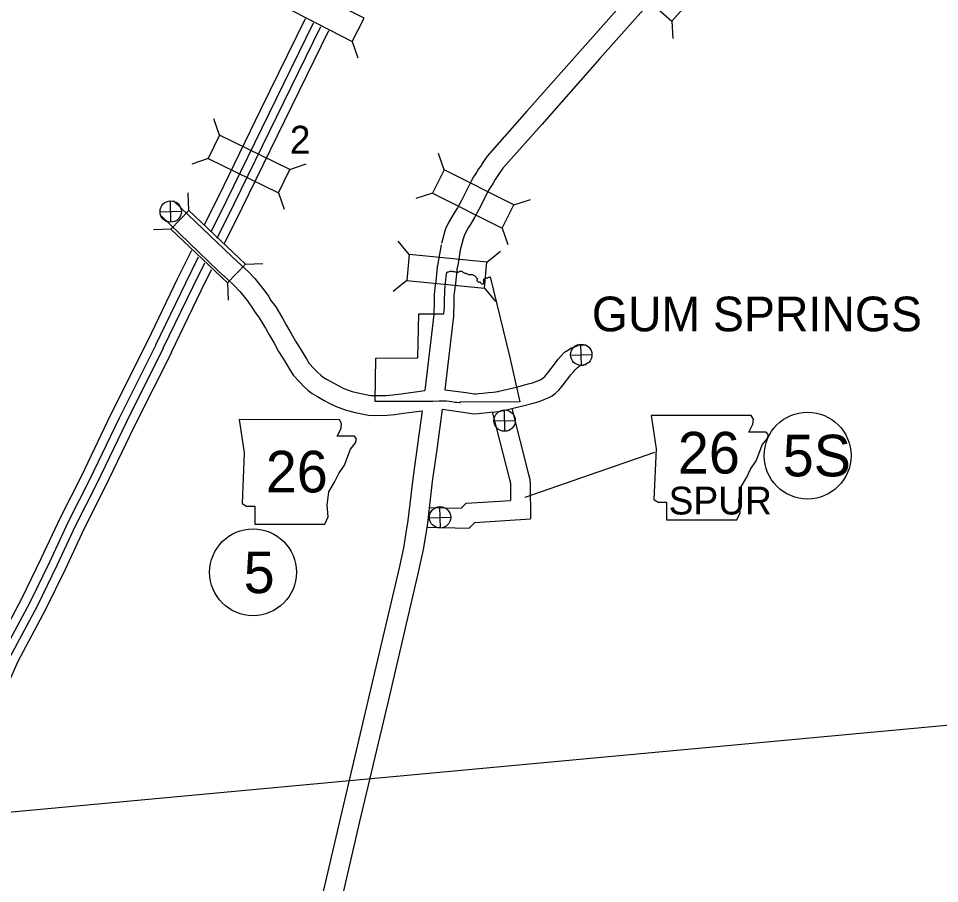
# Model space of a CAD drawing. Extents: x 1369979 to 1371646, y 379997 to 381064.
# Drawn here: x 1370321.9 to 1370431.4, y 380878.2 to 380981.1 of the extents above; entities that cross this region are included whole.
import ezdxf

# ---------------------------------------------------------------- set-up
doc = ezdxf.new("R2010")
doc.units = 0
doc.layers.add('R_Border Notes', color=7, linetype='Continuous')
doc.layers.add('R_Draft', color=7, linetype='Continuous')

msp = doc.modelspace()

# ---------------------------------------------------------------- linework, layer by layer
at = {"layer": 'R_Border Notes'}
for p, q in [((1370399.53, 380980.71), (1370399.66, 380978.65)), ((1370361.57, 380978.31), (1370362.21, 380976.35)), ((1370345.8, 380967.18), (1370345.13, 380969.13)), ((1370372.47, 380963.05), (1370371.82, 380965)), ((1370344.44, 380964.4), (1370342.49, 380963.73)), ((1370354.14, 380963.11), (1370356.09, 380963.78)), ((1370342.13, 380958.24), (1370342.07, 380960.31)), ((1370352.79, 380960.33), (1370353.46, 380958.38)), ((1370371.09, 380960.28), (1370369.13, 380959.63)), ((1370340.02, 380956.82), (1370339.97, 380959.37)), ((1370380.77, 380958.89), (1370382.73, 380959.54)), ((1370338.72, 380958.07), (1370341.27, 380958.13)), ((1370340, 380956), (1370337.94, 380955.94)), ((1370379.39, 380956.12), (1370380.04, 380954.17)), ((1370368.34, 380952.98), (1370367.03, 380954.57)), ((1370377.57, 380952.07), (1370379.17, 380953.38)), ((1370348.87, 380951.86), (1370350.93, 380951.92)), ((1370346.74, 380949.62), (1370346.8, 380947.55)), ((1370368.03, 380949.9), (1370366.44, 380948.59)), ((1370377.27, 380948.99), (1370378.58, 380947.4)), ((1370388.8, 380939.8), (1370388.74, 380942.34)), ((1370387.49, 380941.04), (1370390.04, 380941.1)), ((1370379.7, 380931.97), (1370379.64, 380934.52)), ((1370378.4, 380933.22), (1370380.94, 380933.27)), ((1370382.12, 380924.14), (1370397.5, 380929.49)), ((1370372.03, 380920.46), (1370371.97, 380923.01)), ((1370370.73, 380921.71), (1370373.28, 380921.76))]:
    msp.add_line(p, q, dxfattribs=at)
for points in [[(1370392.59, 380986.86), (1370399.53, 380980.71), (1370401.59, 380983.02), (1370394.64, 380989.18)], [(1370362.98, 380981.07), (1370354.71, 380985.28), (1370353.31, 380982.53), (1370361.57, 380978.31)], [(1370354.14, 380963.11), (1370345.8, 380967.18), (1370344.44, 380964.4), (1370352.79, 380960.33)], [(1370380.77, 380958.89), (1370372.47, 380963.05), (1370371.09, 380960.28), (1370379.39, 380956.12)], [(1370348.87, 380951.86), (1370342.13, 380958.24), (1370340, 380956), (1370346.74, 380949.62)], [(1370377.57, 380952.07), (1370368.34, 380952.98), (1370368.03, 380949.9), (1370377.27, 380948.99)], [(1370348.14, 380933.37), (1370348.73, 380929.4), (1370348.47, 380923.39), (1370349, 380923.06), (1370349.99, 380923.06), (1370349.99, 380920.94), (1370358.32, 380920.94), (1370358.71, 380921.8), (1370358.58, 380923.19), (1370358.78, 380924.78), (1370359.51, 380926.03), (1370359.97, 380926.96), (1370360.63, 380927.95), (1370361.03, 380929.01), (1370361.36, 380929.86), (1370361.95, 380930.59), (1370362.08, 380931.05), (1370361.82, 380931.38), (1370359.77, 380931.38), (1370360.23, 380932.31), (1370360.3, 380932.9), (1370360.03, 380933.36)], [(1370397.07, 380933.87), (1370397.66, 380929.9), (1370397.4, 380923.89), (1370397.93, 380923.56), (1370398.92, 380923.56), (1370398.92, 380921.44), (1370407.25, 380921.44), (1370407.64, 380922.3), (1370407.51, 380923.69), (1370407.71, 380925.27), (1370408.44, 380926.53), (1370408.9, 380927.46), (1370409.56, 380928.45), (1370409.96, 380929.5), (1370410.29, 380930.36), (1370410.88, 380931.09), (1370411.01, 380931.55), (1370410.75, 380931.88), (1370408.7, 380931.88), (1370409.16, 380932.81), (1370409.23, 380933.4), (1370408.96, 380933.86)]]:
    msp.add_lwpolyline(points, close=True, dxfattribs=at)
for points in [[(1370397.99, 380987.73), (1370389.22, 380977.83), (1370382.32, 380970.01), (1370377.6, 380964.69), (1370377.08, 380963.91), (1370376.79, 380963.47), (1370376.57, 380963.17), (1370376.33, 380962.75), (1370376.16, 380962.5), (1370375.98, 380962.24), (1370375.73, 380961.8), (1370374.54, 380959.43), (1370374.06, 380958.54), (1370373.65, 380957.86), (1370373.35, 380957.38), (1370372.97, 380956.72), (1370372.65, 380956.05), (1370372.49, 380955.5), (1370372.15, 380954.28)], [(1370399.74, 380986.17), (1370390.98, 380976.28), (1370384.07, 380968.45), (1370379.46, 380963.26), (1370379.03, 380962.61), (1370378.71, 380962.14), (1370378.55, 380961.91), (1370378.31, 380961.49), (1370378.09, 380961.17), (1370377.97, 380961), (1370377.79, 380960.69), (1370376.62, 380958.34), (1370376.09, 380957.39), (1370375.65, 380956.64), (1370375.35, 380956.16), (1370375.05, 380955.64), (1370374.85, 380955.22), (1370374.74, 380954.85), (1370374.41, 380953.65)], [(1370343.98, 380956.49), (1370345.69, 380959.93), (1370350.7, 380970.21), (1370356, 380981.04)], [(1370344.78, 380955.69), (1370346.65, 380959.46), (1370351.67, 380969.74), (1370356.96, 380980.54)], [(1370345.5, 380954.93), (1370347.53, 380959.02), (1370352.55, 380969.31), (1370357.82, 380980.09)], [(1370346.34, 380954.21), (1370348.49, 380958.55), (1370353.51, 380968.84), (1370358.79, 380979.62)], [(1370340.34, 380959.39), (1370347.27, 380952.74), (1370348.38, 380951.73), (1370349.18, 380950.96), (1370349.97, 380950.13), (1370350.41, 380949.59), (1370350.93, 380948.96), (1370351.6, 380948.02), (1370351.89, 380947.54), (1370352.47, 380946.79), (1370353.29, 380945.41), (1370353.75, 380944.57), (1370354.32, 380943.59), (1370354.8, 380942.69), (1370355.38, 380941.81), (1370356.13, 380940.59), (1370356.45, 380940.04), (1370356.98, 380939.46), (1370357.48, 380938.95), (1370357.81, 380938.64), (1370358.1, 380938.43), (1370358.52, 380938.18), (1370359.44, 380937.65), (1370359.96, 380937.37), (1370360.56, 380937.08), (1370361.55, 380936.72), (1370362.42, 380936.5), (1370363.18, 380936.34), (1370363.75, 380936.23), (1370364.34, 380936.22), (1370365.6, 380936.25), (1370366.38, 380936.31), (1370367.36, 380936.45), (1370370.18, 380936.81)], [(1370338.72, 380957.7), (1370345.68, 380951.02), (1370346.78, 380950.02), (1370347.52, 380949.31), (1370348.21, 380948.58), (1370348.6, 380948.1), (1370349.07, 380947.53), (1370349.64, 380946.73), (1370349.96, 380946.21), (1370350.52, 380945.47), (1370351.26, 380944.24), (1370351.7, 380943.43), (1370352.27, 380942.45), (1370352.79, 380941.48), (1370353.4, 380940.56), (1370354.12, 380939.38), (1370354.56, 380938.64), (1370355.28, 380937.85), (1370355.84, 380937.27), (1370356.32, 380936.83), (1370356.81, 380936.46), (1370357.35, 380936.15), (1370358.29, 380935.61), (1370358.89, 380935.28), (1370359.65, 380934.92), (1370360.85, 380934.48), (1370361.89, 380934.22), (1370362.72, 380934.04), (1370363.5, 380933.89), (1370364.35, 380933.87), (1370365.72, 380933.91), (1370366.63, 380933.98), (1370367.67, 380934.13), (1370369.87, 380934.41)], [(1370372.12, 380954.16), (1370371.82, 380952.35), (1370371.68, 380951.7), (1370371.65, 380951.56), (1370371.63, 380951.07), (1370371.59, 380950.62), (1370371.5, 380949.82), (1370371.39, 380949.05), (1370371.28, 380948.19), (1370371.3, 380946.96), (1370371.26, 380946.26), (1370371.25, 380945.87), (1370370.18, 380936.81)], [(1370374.43, 380953.77), (1370374.13, 380951.91), (1370373.98, 380951.26), (1370373.98, 380950.93), (1370373.92, 380950.38), (1370373.83, 380949.53), (1370373.72, 380948.73), (1370373.63, 380948.06), (1370373.65, 380946.91), (1370373.6, 380946.14), (1370373.58, 380945.68), (1370372.55, 380936.92)], [(1370337.26, 380942.73), (1370340.81, 380950.1), (1370342.5, 380953.52)], [(1370338.23, 380942.27), (1370341.77, 380949.63), (1370343.31, 380952.72)], [(1370339.11, 380941.84), (1370342.65, 380949.2), (1370344.05, 380952.02)], [(1370340.08, 380941.38), (1370343.61, 380948.73), (1370344.85, 380951.22)], [(1370377.96, 380950.35), (1370380.27, 380940.75), (1370381.47, 380935.48), (1370374.33, 380935.43), (1370374.33, 380935.35), (1370374.27, 380935.36), (1370373.99, 380935.39), (1370373.77, 380935.41), (1370373.39, 380935.47), (1370373.06, 380935.52), (1370372.75, 380935.55), (1370372.41, 380935.57), (1370371.88, 380935.56), (1370371.13, 380935.53), (1370364.29, 380935.52), (1370364.35, 380940.68), (1370369.36, 380940.7), (1370369.46, 380945.93), (1370372.46, 380945.94)], [(1370372.46, 380945.94), (1370372.49, 380946.33), (1370372.52, 380946.79), (1370372.53, 380947.26), (1370372.54, 380947.71), (1370372.56, 380948.39), (1370372.58, 380948.81), (1370372.6, 380949.12), (1370372.64, 380949.57), (1370372.73, 380950.37), (1370372.81, 380950.91)], [(1370372.81, 380950.91), (1370372.88, 380950.91), (1370372.93, 380950.92), (1370372.98, 380950.93), (1370373.1, 380950.99), (1370373.19, 380951.02), (1370373.26, 380951.03), (1370373.32, 380951.03), (1370373.38, 380951.02), (1370373.46, 380950.98), (1370373.52, 380950.97), (1370373.59, 380950.97), (1370373.68, 380950.97), (1370373.78, 380950.95), (1370373.92, 380950.91), (1370374.01, 380950.9), (1370374.08, 380950.9), (1370374.15, 380950.91), (1370374.31, 380950.99), (1370374.36, 380951.01), (1370374.4, 380951.02), (1370374.45, 380951.02), (1370374.47, 380951.02), (1370374.51, 380951.02), (1370374.57, 380951), (1370374.72, 380950.91), (1370374.86, 380950.83), (1370374.94, 380950.79), (1370375.05, 380950.76), (1370375.15, 380950.73), (1370375.24, 380950.68), (1370375.32, 380950.63), (1370375.38, 380950.62), (1370375.77, 380950.61), (1370375.84, 380950.6), (1370375.9, 380950.59), (1370375.94, 380950.55), (1370375.98, 380950.52), (1370376.13, 380950.44), (1370376.18, 380950.41), (1370376.22, 380950.39), (1370376.24, 380950.3), (1370376.27, 380950.25), (1370376.31, 380950.2), (1370376.38, 380950.16), (1370376.39, 380950.13), (1370376.4, 380950.08), (1370376.4, 380950.04), (1370376.36, 380949.98), (1370376.35, 380949.95), (1370376.36, 380949.92), (1370376.39, 380949.87), (1370376.42, 380949.83), (1370376.47, 380949.78), (1370376.53, 380949.74), (1370376.6, 380949.7), (1370376.65, 380949.68), (1370376.67, 380949.69), (1370376.68, 380949.72), (1370376.69, 380949.76), (1370376.72, 380949.76), (1370376.75, 380949.74), (1370376.78, 380949.68), (1370376.83, 380949.62), (1370376.89, 380949.56), (1370376.97, 380949.52), (1370377.05, 380949.5), (1370377.11, 380949.5), (1370377.16, 380949.53), (1370377.19, 380949.56), (1370377.2, 380949.6), (1370377.21, 380949.64), (1370377.18, 380949.84), (1370377.17, 380949.93), (1370377.18, 380949.99), (1370377.2, 380950.05), (1370377.23, 380950.1), (1370377.28, 380950.13), (1370377.36, 380950.17), (1370377.46, 380950.21), (1370377.51, 380950.21), (1370377.57, 380950.22), (1370377.64, 380950.21), (1370377.68, 380950.22), (1370377.7, 380950.27), (1370377.73, 380950.3), (1370377.78, 380950.3), (1370377.84, 380950.3), (1370377.87, 380950.3), (1370377.9, 380950.31), (1370377.96, 380950.35)], [(1370337.28, 380942.76), (1370332.89, 380934), (1370329.34, 380926.6), (1370326.84, 380921.69), (1370324.61, 380916.89), (1370322.29, 380912.13), (1370319, 380905.97), (1370317.85, 380903.39), (1370316.93, 380901.7), (1370315.72, 380900.05), (1370313.97, 380898.07), (1370307.68, 380890.57), (1370300.8, 380882.32)], [(1370338.24, 380942.27), (1370333.86, 380933.53), (1370330.3, 380926.13), (1370327.81, 380921.22), (1370325.58, 380916.43), (1370323.25, 380911.64), (1370319.97, 380905.5), (1370318.82, 380902.92), (1370317.84, 380901.13), (1370316.56, 380899.37), (1370314.78, 380897.36), (1370308.51, 380889.88), (1370301.6, 380881.6)], [(1370339.11, 380941.84), (1370334.73, 380933.1), (1370331.18, 380925.69), (1370328.69, 380920.79), (1370326.46, 380916.01), (1370324.12, 380911.2), (1370320.84, 380905.07), (1370319.69, 380902.48), (1370318.67, 380900.6), (1370317.32, 380898.76), (1370315.52, 380896.73), (1370309.26, 380889.26), (1370302.36, 380880.99)], [(1370378.81, 380936.7), (1370381.25, 380937.28), (1370382.47, 380937.61), (1370382.97, 380937.73), (1370383.29, 380937.84), (1370383.51, 380937.93), (1370383.83, 380938.07), (1370384.05, 380938.19), (1370384.23, 380938.32), (1370384.43, 380938.48), (1370384.79, 380938.94), (1370385.71, 380940.13), (1370386.04, 380940.56), (1370386.33, 380940.9), (1370386.8, 380941.37), (1370387.24, 380941.68), (1370387.54, 380941.84), (1370388.01, 380942.02), (1370388.14, 380942.05), (1370388.47, 380942.22), (1370389.24, 380942.25)], [(1370340.07, 380941.36), (1370335.7, 380932.63), (1370332.14, 380925.22), (1370329.65, 380920.33), (1370327.43, 380915.55), (1370325.07, 380910.71), (1370321.81, 380904.6), (1370320.66, 380902.01), (1370319.58, 380900.03), (1370318.16, 380898.09), (1370316.34, 380896.03), (1370310.08, 380888.57), (1370303.21, 380880.34)], [(1370379.36, 380934.42), (1370381.83, 380935.01), (1370383.05, 380935.34), (1370383.64, 380935.48), (1370384.15, 380935.66), (1370384.44, 380935.78), (1370384.86, 380935.97), (1370385.3, 380936.2), (1370385.67, 380936.47), (1370386.12, 380936.85), (1370386.63, 380937.5), (1370387.55, 380938.69), (1370387.85, 380939.06), (1370388.05, 380939.3), (1370388.32, 380939.58), (1370388.48, 380939.69), (1370388.52, 380939.71), (1370388.7, 380939.78), (1370388.96, 380939.84), (1370389.08, 380939.9), (1370389.34, 380939.91)], [(1370372.55, 380936.92), (1370375.08, 380936.57), (1370376.05, 380936.42), (1370376.3, 380936.44), (1370376.57, 380936.48), (1370377.07, 380936.52), (1370377.39, 380936.55), (1370377.76, 380936.59), (1370378.32, 380936.64), (1370378.94, 380936.72)], [(1370369.87, 380934.41), (1370369.32, 380930.41), (1370368.75, 380926.32), (1370368.18, 380921.37), (1370367.89, 380919.66), (1370367.69, 380918.33), (1370367.16, 380915.92), (1370363.57, 380900.6), (1370360.15, 380886.11), (1370355.78, 380867.24), (1370353.47, 380857.56), (1370352.9, 380855.68)], [(1370372.26, 380934.59), (1370371.64, 380930.09), (1370371.07, 380926.02), (1370370.5, 380921.04), (1370370.21, 380919.3), (1370370, 380917.91), (1370369.44, 380915.39), (1370365.85, 380900.06), (1370362.43, 380885.58), (1370358.06, 380866.71), (1370355.74, 380856.94), (1370355.14, 380854.99)], [(1370372.26, 380934.59), (1370374.74, 380934.25), (1370375.98, 380934.06), (1370376.57, 380934.11), (1370376.83, 380934.15), (1370377.26, 380934.19), (1370377.61, 380934.22), (1370377.98, 380934.25), (1370378.57, 380934.31), (1370379.24, 380934.39)], [(1370378.2, 380934.29), (1370380.23, 380926.24), (1370380.35, 380925.83), (1370380.38, 380925.56), (1370380.38, 380923.76)], [(1370380.52, 380934.68), (1370382.49, 380926.85), (1370382.65, 380926.3), (1370382.72, 380925.71), (1370382.73, 380921.56)], [(1370370.74, 380922.93), (1370374.5, 380922.83), (1370375.09, 380923.42), (1370380.38, 380923.76)], [(1370370.44, 380920.6), (1370375.44, 380920.46), (1370376.12, 380921.14), (1370382.73, 380921.56)]]:
    msp.add_lwpolyline(points, dxfattribs=at)
for centre, radius in [((1370339.99, 380958.1), 1.27), ((1370388.77, 380941.07), 1.27), ((1370379.67, 380933.25), 1.27), ((1370415.67, 380929.09), 5.16), ((1370372, 380921.74), 1.27), ((1370349.77, 380915.22), 5.16)]:
    msp.add_circle(centre, radius, dxfattribs=at)
at = {"layer": 'R_Draft'}
msp.add_line((1370271.68, 380882.17), (1370489.61, 380902.37), dxfattribs=at)

# ---------------------------------------------------------------- texts
at = {"layer": 'R_Border Notes'}
for s, height, p in [('2', 3.3, (1370354.14, 380964.99)), ('GUM SPRINGS', 4.125, (1370390.03, 380943.86)), ('26', 4.95, (1370400.26, 380926.96)), ('5S', 4.95, (1370412.72, 380926.62)), ('26', 4.95, (1370351.29, 380924.71)), ('SPUR', 3.3, (1370399.16, 380922.09)), ('5', 4.95, (1370348.66, 380912.74))]:
    msp.add_text(s, height=height, dxfattribs=at).set_placement(p)

doc.saveas('drawing.dxf')
